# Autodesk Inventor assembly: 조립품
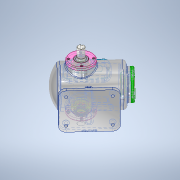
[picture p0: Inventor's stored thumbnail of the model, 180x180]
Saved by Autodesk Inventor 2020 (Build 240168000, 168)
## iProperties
Created: 2021-11
Part Number: 조립품
Document SubType Name: Assembly
Designer: USER
Author: USER
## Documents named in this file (13)
- C:\Users\USER\Desktop\711106V1042\조립품.iam
- C:\Users\USER\Desktop\711106V1042\본체.ipt
- C:\Users\USER\Desktop\711106V1042\베어링 6205.ipt
- 베어링 6205.ipt
- C:\Users\USER\Desktop\711106V1042\축 커버.ipt
- C:\Users\USER\Desktop\711106V1042\볼트 M4x0.7.ipt
- C:\Users\USER\Desktop\711106V1042\편심축.ipt
- C:\Users\USER\Desktop\711106V1042\상부커버.ipt
- C:\Users\USER\Desktop\711106V1042\육각머리볼트 M4.ipt
- C:\Users\USER\Desktop\711106V1042\오일실.ipt
- 오일실.ipt
- C:\Users\USER\Desktop\711106V1042\슬라이드 커버.ipt
- C:\Users\USER\Desktop\711106V1042\부시.ipt
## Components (12 placed, 1 different names)
1. M4x0.7:2
2. M4x0.7:3
3. M4x0.7:4
4. M4x0.7:5
5. M4x0.7:10
6. M4x0.7:11
7. M4x0.7:12
8. M4x0.7:13
9. M4x0.7:9
10. M4x0.7:14
11. M4x0.7:15
12. M4x0.7:16
